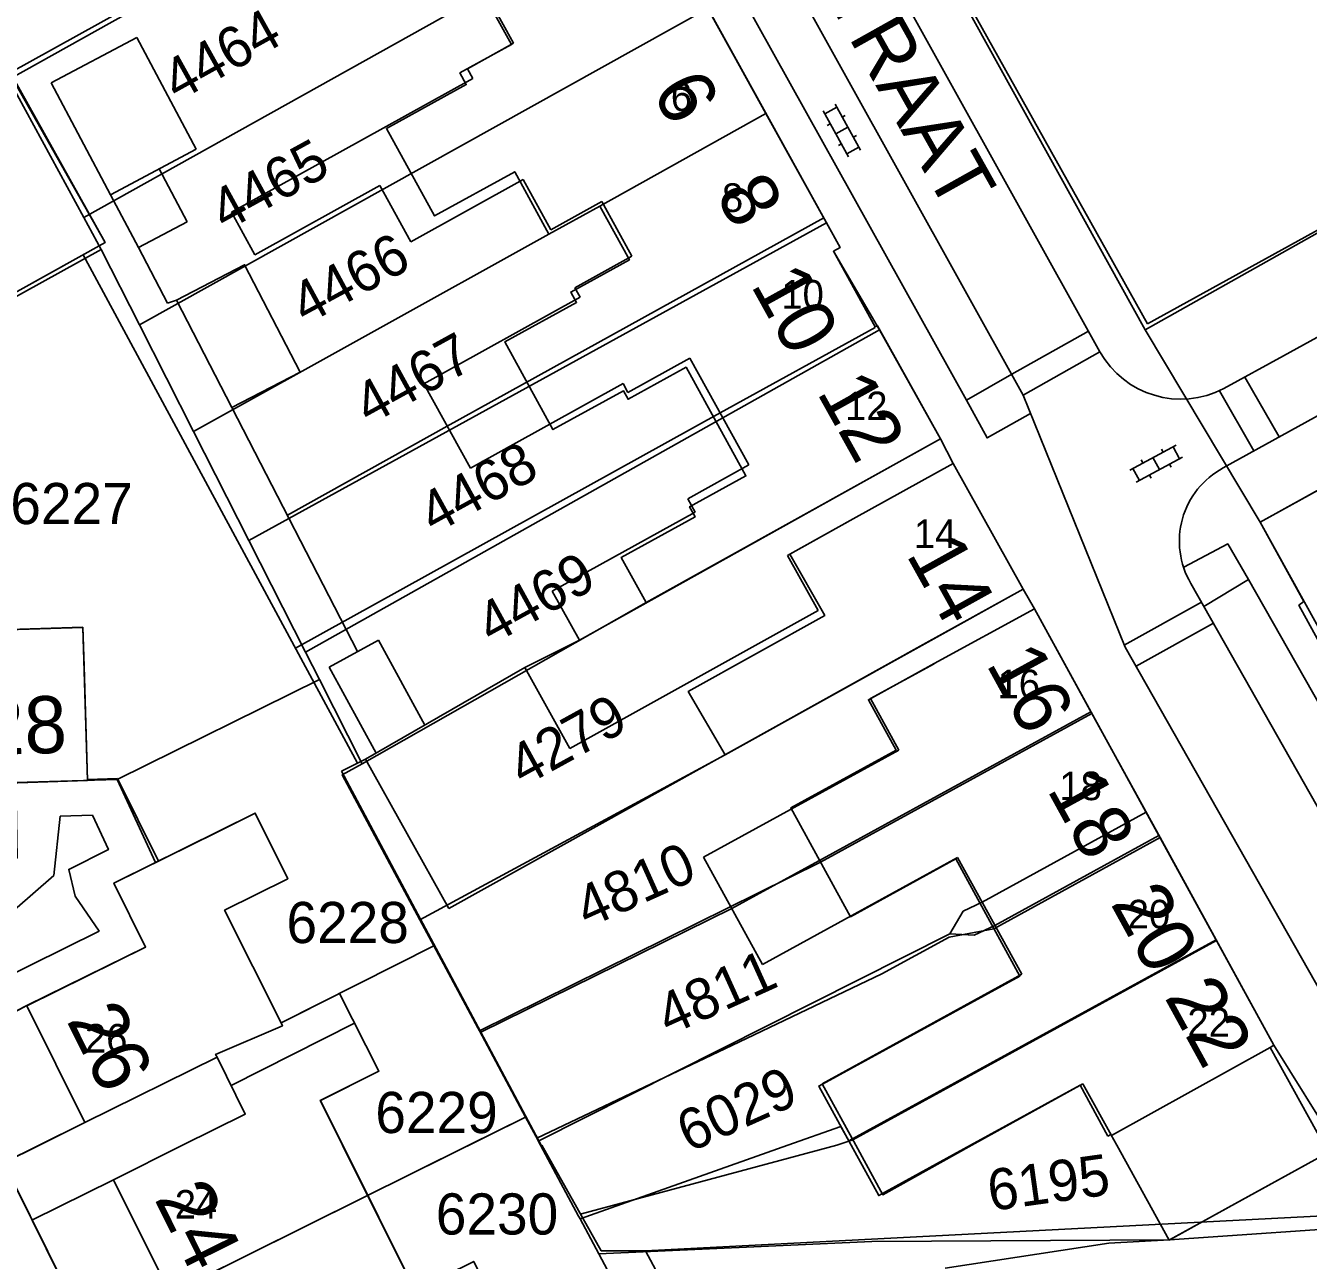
# Model space of a CAD drawing. Extents: x 148816 to 151297, y 399515 to 402500.
# Drawn here: x 150198.8 to 150254.9, y 399995 to 400049 of the extents above; entities that cross this region are included whole.
import ezdxf

# ---------------------------------------------------------------- set-up
doc = ezdxf.new("R2010")
doc.units = 0
for name, color, linetype in [('B01 Hoofdgebouw  [D] Norm', 7, 'Continuous'), ('B01 Hoofdgebouw  [T] Norm', 7, 'Continuous'), ('B01 hoofgebouw', 7, 'Continuous'), ('B02 Bijgebouw  [D] Norm', 7, 'Continuous'), ('B07 Tussenmuur  [D] Norm', 7, 'Continuous'), ('G01 perceelsgrens', 7, 'Continuous'), ('S02 Open verharding  Norm', 7, 'Continuous'), ('T04 Haag heg  [D] Gem', 7, 'Continuous'), ('T09 Insteek water  [D] Norm', 7, 'Continuous'), ('V00 Kant verharding algemeen  [T] Norm', 7, 'Continuous'), ('V00 Kant verharding algemeen secundair  [T] Gem', 7, 'Continuous'), ('V06 Kant onverhard  [T] Gem', 7, 'Continuous'), ('Z01 perceelnummer', 7, 'Continuous'), ('Z02 huisnummer', 7, 'Continuous'), ('Z02 Huisnummer  [Tekst] Norm', 7, 'Continuous'), ('Z06 straatnaam', 7, 'Continuous')]:
    doc.layers.add(name, color=color, linetype=linetype)

msp = doc.modelspace()

# ---------------------------------------------------------------- linework, layer by layer
at = {"layer": 'B01 Hoofdgebouw  [D] Norm'}
for p, q in [((150198.007, 400046.867), (150209.022, 400052.993)), ((150220.109, 400048.214), (150217.755, 400052.466)), ((150218.088, 400047.095), (150220.109, 400048.214)), ((150218.326, 400046.665), (150218.088, 400047.095)), ((150202.24, 400039.49), (150198.106, 400046.922)), ((150207.765, 400040.82), (150218.326, 400046.665)), ((150204.609, 400042.718), (150205.838, 400040.401)), ((150214.252, 400041.98), (150208.794, 400038.96)), ((150215.611, 400039.525), (150214.252, 400041.98)), ((150220.524, 400042.245), (150215.611, 400039.525)), ((150221.74, 400040.049), (150220.524, 400042.245)), ((150203.703, 400039.268), (150202.474, 400041.586)), ((150223.964, 400041.28), (150221.74, 400040.049)), ((150225.285, 400038.894), (150223.964, 400041.28)), ((150205.838, 400040.401), (150203.703, 400039.268)), ((150208.794, 400038.96), (150207.765, 400040.82)), ((150185.558, 400030.21), (150202.24, 400039.49)), ((150222.795, 400037.515), (150225.285, 400038.894)), ((150223.027, 400037.096), (150222.795, 400037.515)), ((150216.179, 400033.304), (150223.027, 400037.096)), ((150227.817, 400034.436), (150225.11, 400032.938)), ((150230.403, 400029.763), (150227.817, 400034.436)), ((150218.218, 400029.622), (150216.179, 400033.304)), ((150224.898, 400033.321), (150218.218, 400029.622)), ((150225.11, 400032.938), (150224.898, 400033.321)), ((150227.729, 400028.283), (150230.403, 400029.763)), ((150222.99, 400022.096), (150234.413, 400028.465)), ((150228.052, 400027.699), (150227.729, 400028.283)), ((150221.802, 400024.242), (150228.052, 400027.699)), ((150232.088, 400025.801), (150234.961, 400027.399)), ((150233.427, 400023.394), (150232.088, 400025.801)), ((150222.99, 400022.096), (150221.802, 400024.242)), ((150222.576, 400017.358), (150233.427, 400023.394)), ((150217.27, 400010.354), (150238.021, 400021.899)), ((150213.636, 400016.885), (150220.602, 400020.907)), ((150220.602, 400020.907), (150222.576, 400017.358)), ((150235.719, 400019.537), (150238.503, 400021.064)), ((150236.955, 400017.284), (150235.719, 400019.537)), ((150228.419, 400012.601), (150236.955, 400017.284)), ((150213.636, 400016.885), (150217.27, 400010.354)), ((150247.771, 400014.57), (150240.601, 400010.638)), ((150248.333, 400013.546), (150241.163, 400009.614)), ((150230.996, 400007.904), (150228.419, 400012.601)), ((150239.532, 400012.587), (150230.996, 400007.904)), ((150242.334, 400007.48), (150239.532, 400012.587)), ((150233.601, 400002.689), (150242.334, 400007.48)), ((150246.26, 400000.426), (150253.2, 400004.27)), ((150235.076, 400000), (150233.601, 400002.689)), ((150240.149, 400000), (150245.005, 400002.691)), ((150245.005, 400002.691), (150246.26, 400000.426))]:
    msp.add_line(p, q, dxfattribs=at)
at = {"layer": 'B01 Hoofdgebouw  [T] Norm'}
for p, q in [((150234.39, 400039.27), (150227.89, 400051.03)), ((150234.1, 400039.11), (150234.39, 400039.27)), ((150235.92, 400035.8), (150234.1, 400039.11)), ((150236.02, 400035.85), (150235.92, 400035.8)), ((150238.78, 400030.9), (150236.02, 400035.85)), ((150234.41, 400028.47), (150238.78, 400030.9)), ((150252.77, 400027.26), (150259.53, 400031.01)), ((150239.33, 400029.83), (150234.96, 400027.4)), ((150242.39, 400024.33), (150239.33, 400029.83)), ((150254.67, 400023.79), (150252.77, 400027.26)), ((150238.02, 400021.9), (150242.39, 400024.33)), ((150238.5, 400021.07), (150242.89, 400023.47)), ((150242.89, 400023.47), (150253.36, 400004.38)), ((150254.46, 400023.62), (150254.67, 400023.79)), ((150255.68, 400021.4), (150254.46, 400023.62)), ((150201.272, 400022.655), (150181.03, 400022.028)), ((150201.272, 400022.655), (150201.479, 400015.96)), ((150201.479, 400015.96), (150195.375, 400015.756)), ((150208.812, 400014.525), (150202.627, 400011.466)), ((150210.231, 400011.657), (150208.812, 400014.525)), ((150207.465, 400010.279), (150210.231, 400011.657)), ((150202.627, 400011.466), (150204.01, 400008.67)), ((150207.465, 400010.279), (150209.944, 400005.351)), ((150204.01, 400008.67), (150198.824, 400006.105)), ((150209.944, 400005.351), (150212.496, 400006.642)), ((150212.496, 400006.642), (150214.218, 400003.238)), ((150201.355, 400000.987), (150198.824, 400006.105)), ((150253.36, 400004.38), (150253.2, 400004.27)), ((150207.143, 400003.85), (150201.355, 400000.987)), ((150207.143, 400003.85), (150208.373, 400001.363)), ((150253.2, 400004.27), (150255.565, 400000)), ((150211.655, 400001.958), (150214.218, 400003.238)), ((150211.655, 400001.958), (150212.631, 400000)), ((150208.372, 400001.365), (150205.633, 400000)), ((150205.633, 400000), (150202.606, 399998.491)), ((150212.631, 400000), (150215.798, 399993.644)), ((150255.74, 399999.68), (150251.36, 399997.27)), ((150202.606, 399998.491), (150207.56, 399988.55))]:
    msp.add_line(p, q, dxfattribs=at)
at = {"layer": 'B01 hoofgebouw'}
for points in [[(150169.09, 400048.69), (150171.369, 400044.618), (150177.805, 400048.221), (150179.199, 400045.731), (150183.06, 400047.893), (150189.217, 400036.824), (150183.613, 400033.707), (150185.558, 400030.21), (150202.24, 400039.49), (150190.33, 400060.58)], [(150234.41, 400028.47), (150238.78, 400030.9), (150236.02, 400035.85), (150235.92, 400035.8), (150234.1, 400039.11), (150234.39, 400039.27), (150227.89, 400051.03), (150227.61, 400050.87), (150225.79, 400054.18), (150225.89, 400054.23), (150223.15, 400059.18), (150218.77, 400056.76)], [(150217.672, 400052.405), (150220.012, 400048.149), (150217.761, 400046.912), (150218.041, 400046.403), (150214.547, 400044.482), (150216.65, 400040.658), (150220.157, 400042.586), (150221.655, 400039.862), (150223.884, 400041.087), (150225.176, 400038.737), (150222.612, 400037.327), (150222.864, 400036.869), (150219.723, 400035.142), (150221.828, 400031.312), (150224.913, 400033.008), (150225.116, 400032.639), (150227.655, 400034.035), (150230.267, 400029.284), (150227.805, 400027.93), (150228.048, 400027.488), (150224.821, 400025.713), (150225.905, 400023.741), (150234.41, 400028.47)], [(150267.14, 400011.57), (150262.77, 400009.14), (150260.84, 400012.62), (150260.61, 400012.49), (150259.37, 400014.72), (150259.51, 400014.8), (150255.83, 400021.48), (150255.68, 400021.4), (150254.46, 400023.62), (150254.67, 400023.79), (150252.77, 400027.26), (150259.53, 400031.01), (150260.79, 400028.73), (150269.62, 400033.65), (150269.921, 400033.111), (150271.89, 400034.2), (150270.35, 400036.98), (150273.44, 400038.69), (150275.85, 400034.31)], [(150238.02, 400021.9), (150242.39, 400024.33), (150239.33, 400029.83), (150234.96, 400027.4)], [(150234.96, 400027.4), (150232.19, 400025.86), (150233.72, 400023.179), (150227.747, 400019.847), (150229.358, 400017.083), (150238.02, 400021.9)], [(150255.563, 400000), (150253.2, 400004.27), (150253.36, 400004.38), (150242.89, 400023.47), (150238.5, 400021.07)], [(150201.27, 400022.66), (150181.03, 400022.03)], [(150201.27, 400022.66), (150201.325, 400020.957)], [(150181.083, 400020.319), (150181.238, 400015.322), (150184.277, 400015.416), (150184.404, 400011.314), (150195.501, 400011.658), (150195.375, 400015.756), (150201.479, 400015.96), (150201.325, 400020.957)], [(150238.5, 400021.07), (150235.63, 400019.492), (150236.842, 400017.28), (150232.233, 400014.755), (150234.839, 400009.997), (150239.449, 400012.522), (150242.253, 400007.403), (150233.456, 400002.584), (150234.871, 400000)], [(150212.635, 400000), (150211.66, 400001.96), (150214.22, 400003.24), (150212.5, 400006.64), (150209.94, 400005.35), (150207.47, 400010.28), (150210.23, 400011.66), (150208.81, 400014.53), (150207.108, 400013.682)], [(150207.108, 400013.682), (150202.627, 400011.466), (150204.01, 400008.67), (150198.824, 400006.105), (150201.355, 400000.987), (150207.143, 400003.85), (150208.372, 400001.365), (150205.633, 400000)], [(150240.095, 400000), (150244.883, 400002.623), (150246.1, 400000.402)], [(150246.1, 400000.402), (150246.232, 400000.474)], [(150246.232, 400000.474), (150246.493, 400000)], [(150205.633, 400000), (150202.606, 399998.491), (150207.56, 399988.55), (150213.32, 399991.421), (150215.846, 399986.318), (150210.088, 399983.468), (150215.017, 399973.51), (150219.498, 399975.728)], [(150223.64, 399977.78), (150219.12, 399986.92), (150221.7, 399988.2), (150218.37, 399994.92), (150215.8, 399993.64), (150212.635, 400000)], [(150234.871, 400000), (150236.077, 399997.799), (150240.095, 400000)], [(150246.493, 400000), (150248.778, 399995.848), (150251.36, 399997.27)], [(150251.36, 399997.27), (150255.74, 399999.68), (150255.563, 400000)]]:
    msp.add_lwpolyline(points, dxfattribs=at)
at = {"layer": 'B02 Bijgebouw  [D] Norm'}
for p, q in [((150199.881, 400046.475), (150203.634, 400048.465)), ((150203.634, 400048.465), (150206.227, 400043.576)), ((150202.474, 400041.586), (150199.881, 400046.475)), ((150206.227, 400043.576), (150202.474, 400041.586)), ((150212.04, 400020.921), (150214.206, 400022.1)), ((150214.206, 400022.1), (150216.228, 400018.382)), ((150214.092, 400017.148), (150212.04, 400020.921))]:
    msp.add_line(p, q, dxfattribs=at)
msp.add_lwpolyline([(150207.793, 400032.274), (150205.36, 400036.973), (150208.344, 400038.518), (150210.777, 400033.819)], close=True, dxfattribs=at)
msp.add_lwpolyline([(150240.149, 400000), (150236.257, 399997.83), (150235.076, 400000)], dxfattribs=at)
at = {"layer": 'B07 Tussenmuur  [D] Norm'}
for p, q in [((150233.674, 400040.566), (150217.2, 400031.461)), ((150233.674, 400040.566), (150217.2, 400031.461)), ((150235.931, 400035.78), (150229.14, 400032.046)), ((150235.931, 400035.78), (150229.14, 400032.046)), ((150245.36, 400018.966), (150229.653, 400010.351)), ((150245.36, 400018.966), (150229.653, 400010.351)), ((150250.852, 400008.953), (150234.949, 400000.231)), ((150250.852, 400008.953), (150234.949, 400000.231)), ((150213.156, 400005.337), (150207.758, 400002.606)), ((150213.156, 400005.337), (150207.758, 400002.606)), ((150213.726, 399997.802), (150205.087, 399993.513)), ((150213.726, 399997.802), (150205.087, 399993.513))]:
    msp.add_line(p, q, dxfattribs=at)
at = {"layer": 'G01 perceelsgrens'}
for points in [[(150321.59, 400076.47), (150308, 400069.2), (150269.6, 400047.96), (150247.733, 400035.669)], [(150247.733, 400035.669), (150235.511, 400057.754)], [(150225.856, 400054.291), (150201.315, 400040.582)], [(150207.073, 400051.69), (150198.036, 400046.619)], [(150228.608, 400049.73), (150203.744, 400035.892)], [(150231.143, 400045.144), (150228.608, 400049.73)], [(150201.315, 400040.582), (150198.036, 400046.619)], [(150231.143, 400045.144), (150223.884, 400041.087), (150221.655, 400039.862), (150206.108, 400031.232)], [(150233.789, 400040.357), (150231.143, 400045.144)], [(150202.074, 400039.184), (150201.315, 400040.582)], [(150233.789, 400040.357), (150208.535, 400026.449)], [(150236.12, 400035.671), (150234.1, 400039.11), (150234.39, 400039.27), (150233.789, 400040.357)], [(150189.018, 400031.962), (150202.074, 400039.184)], [(150202.074, 400039.184), (150203.744, 400035.892)], [(150252.77, 400027.26), (150259.53, 400031.01), (150274.51, 400039.29)], [(150203.744, 400035.892), (150206.108, 400031.232)], [(150236.12, 400035.671), (150211.007, 400021.575)], [(150238.78, 400030.9), (150236.12, 400035.671)], [(150247.733, 400035.669), (150252.77, 400027.26)], [(150206.108, 400031.232), (150208.535, 400026.449)], [(150238.78, 400030.9), (150225.905, 400023.741), (150213.485, 400016.692)], [(150242.39, 400024.33), (150239.33, 400029.83), (150238.78, 400030.9)], [(150255.302, 400022.673), (150252.77, 400027.26)], [(150208.535, 400026.449), (150211.007, 400021.575)], [(150242.39, 400024.33), (150229.358, 400017.083), (150216.007, 400009.866)], [(150242.89, 400023.47), (150242.39, 400024.33)], [(150245.405, 400018.884), (150242.89, 400023.47)], [(150211.007, 400021.575), (150211.613, 400020.381)], [(150202.769, 400016.002), (150211.613, 400020.381)], [(150211.613, 400020.381), (150213.485, 400016.692)], [(150245.405, 400018.884), (150233.536, 400012.379), (150218.614, 400004.998)], [(150248.382, 400013.456), (150245.405, 400018.884)], [(150213.485, 400016.692), (150212.612, 400016.205), (150216.007, 400009.866)], [(150190.038, 400008.511), (150193.08, 400008.61), (150195.55, 400010.11), (150198.39, 400012.57), (150198.34, 400015.87), (150202.769, 400016.002)], [(150196.99, 400005.18), (150198.82, 400006.11), (150204.01, 400008.67), (150202.63, 400011.47), (150204.449, 400012.371), (150202.769, 400016.002)], [(150248.382, 400013.456), (150241.119, 400009.473), (150239.16, 400009.095), (150236.215, 400007.495), (150229.651, 400004.365), (150221.123, 400000.315)], [(150250.835, 400008.983), (150248.382, 400013.456)], [(150216.007, 400009.866), (150216.622, 400008.717)], [(150250.835, 400008.983), (150234.767, 400000.192), (150234.42, 400000.825), (150232.099, 400000)], [(150253.36, 400004.38), (150250.835, 400008.983)], [(150199.37, 400000), (150201.36, 400000.99), (150207.14, 400003.85), (150207.078, 400003.975), (150210.001, 400005.229), (150209.94, 400005.35), (150216.622, 400008.717)], [(150216.622, 400008.717), (150218.543, 400005.13)], [(150218.543, 400005.13), (150218.614, 400004.998)], [(150218.614, 400004.998), (150220.632, 400001.231)], [(150256.08, 400000), (150253.36, 400004.38)], [(150218.153, 400000), (150220.632, 400001.231)], [(150220.632, 400001.231), (150221.076, 400000.403)], [(150197.817, 399999.227), (150199.37, 400000)], [(150201.516, 399991.739), (150218.153, 400000)], [(150221.076, 400000.403), (150221.123, 400000.315)], [(150221.123, 400000.315), (150221.292, 400000)], [(150221.292, 400000), (150222.951, 399996.902)], [(150232.099, 400000), (150223.02, 399996.773)], [(150255.74, 399999.68), (150248.798, 399995.86)], [(150197.817, 399999.227), (150201.516, 399991.739)], [(150222.951, 399996.902), (150223.02, 399996.773)], [(150223.02, 399996.773), (150223.834, 399995.252)], [(150258.107, 399996.501), (150248.798, 399995.86)], [(150248.798, 399995.86), (150235.782, 399995.794), (150223.834, 399995.252)], [(150248.798, 399995.86), (150246.146, 399995.711), (150238.992, 399994.623)], [(150223.834, 399995.252), (150224.598, 399993.826)]]:
    msp.add_lwpolyline(points, dxfattribs=at)
at = {"layer": 'S02 Open verharding  Norm'}
for p, q in [((150234.243, 400045.41), (150233.719, 400045.119)), ((150235.286, 400043.53), (150234.171, 400045.541)), ((150234.761, 400043.239), (150233.646, 400045.25)), ((150234.486, 400044.973), (150234.617, 400045.045)), ((150233.83, 400044.609), (150233.961, 400044.682)), ((150234.204, 400044.245), (150234.728, 400044.535)), ((150234.315, 400043.735), (150234.446, 400043.807)), ((150235.213, 400043.661), (150234.689, 400043.37)), ((150234.971, 400044.098), (150235.102, 400044.171)), ((150247.061, 400029.54), (150249.087, 400030.63)), ((150248.443, 400030.454), (150248.514, 400030.322)), ((150249.239, 400030.031), (150248.954, 400030.559)), ((150247.478, 400029.083), (150247.193, 400029.611)), ((150247.345, 400029.012), (150249.371, 400030.102)), ((150247.562, 400029.98), (150247.634, 400029.848)), ((150248.074, 400030.085), (150248.358, 400029.557)), ((150248.798, 400029.794), (150248.87, 400029.662)), ((150247.918, 400029.32), (150247.989, 400029.188))]:
    msp.add_line(p, q, dxfattribs=at)
at = {"layer": 'T04 Haag heg  [D] Gem'}
for p, q in [((150203.703, 400039.268), (150204.968, 400036.841)), ((150201.286, 400038.959), (150213.282, 400016.709)), ((150204.968, 400036.841), (150205.36, 400036.973)), ((150207.793, 400032.274), (150213.289, 400021.601)), ((150210.574, 400021.743), (150229.14, 400032.046)), ((150210.216, 400027.568), (150217.2, 400031.461)), ((150220.602, 400020.907), (150222.99, 400022.096)), ((150213.636, 400016.885), (150212.587, 400016.363)), ((150212.587, 400016.363), (150221.314, 400000)), ((150239.771, 400010.235), (150240.601, 400010.638)), ((150218.675, 400004.948), (150229.653, 400010.351)), ((150239.188, 400009.245), (150239.771, 400010.235)), ((150240.255, 400009.195), (150241.163, 400009.614)), ((150221.214, 400000.187), (150239.188, 400009.245)), ((150239.188, 400009.245), (150240.255, 400009.195)), ((150220.652, 400001.241), (150213.726, 399997.802)), ((150234.25, 400000), (150234.949, 400000.231))]:
    msp.add_line(p, q, dxfattribs=at)
for points in [[(150223.075, 399997.001), (150234.25, 400000)], [(150223.939, 399995.38), (150225.884, 399995.373), (150257.216, 399996.996)], [(150225.884, 399995.373), (150233.942, 399980.307), (150240.091, 399968.532)]]:
    msp.add_lwpolyline(points, dxfattribs=at)
at = {"layer": 'T09 Insteek water  [D] Norm'}
msp.add_line((150221.341, 400000), (150223.939, 399995.38), dxfattribs=at)
at = {"layer": 'V00 Kant verharding algemeen  [T] Norm'}
for p, q in [((150247.83, 400035.93), (150218.97, 400087.67)), ((150269.6, 400047.96), (150247.83, 400035.93)), ((150201.478, 400015.998), (150202.791, 400016.039)), ((150204.576, 400012.43), (150202.791, 400016.039)), ((150199.364, 400000), (150201.355, 400000.987)), ((150197.8, 399999.225), (150199.364, 400000)), ((150199.04, 399996.724), (150202.606, 399998.491))]:
    msp.add_line(p, q, dxfattribs=at)
for points in [[(150216.929, 400086.59), (150213.538, 400084.74), (150242.403, 400032.818), (150246.853, 400021.795), (150259.22, 400000)], [(150245.757, 400034.712), (150216.929, 400086.59)], [(150253.786, 400034.528), (150271.346, 400044.205), (150270.799, 400045.226), (150312.59, 400068.332), (150313.143, 400067.336), (150318.955, 400070.533), (150320.405, 400067.934), (150301.443, 400057.442)], [(150253.786, 400034.528), (150251.17, 400033.101)], [(150241.905, 400033.738), (150239.914, 400032.602), (150240.82, 400030.947), (150242.721, 400032.015)], [(150251.143, 400029.629), (150256.998, 400032.863)], [(150250.298, 400023.573), (150252.251, 400024.743), (150251.343, 400026.307), (150249.425, 400025.285)], [(150263.661, 400000), (150249.733, 400024.582)], [(150198.825, 400006.109), (150197.033, 400005.144)], [(150197.416, 400000), (150211.253, 399972.084)]]:
    msp.add_lwpolyline(points, dxfattribs=at)
for centre, radius, start, end in [((150249.293, 400036.695), 4.054, 209.2818, 297.5704), ((150252.859, 400026.429), 3.631, 118.2061, 210.576)]:
    msp.add_arc(centre, radius, start, end, dxfattribs=at)
at = {"layer": 'V00 Kant verharding algemeen secundair  [T] Gem'}
msp.add_line((150199.998, 400011.806), (150200.283, 400014.401), dxfattribs=at)
for points in [[(150241.897, 400033.734), (150245.256, 400035.614)], [(150245.757, 400034.712), (150242.404, 400032.816)], [(150253.601, 400030.987), (150252.093, 400033.604)], [(150250.979, 400033.007), (150252.488, 400030.377)], [(150246.818, 400021.883), (150250.196, 400023.754)], [(150250.721, 400022.835), (150247.332, 400020.951)], [(150199.998, 400011.806), (150196.54, 400008.791), (150193.709, 400007.085), (150194.454, 400005.653), (150201.98, 400009.367), (150200.937, 400010.9), (150200.65, 400012.066), (150202.388, 400012.932), (150201.69, 400014.44), (150200.283, 400014.401)]]:
    msp.add_lwpolyline(points, dxfattribs=at)
at = {"layer": 'V06 Kant onverhard  [T] Gem'}
for points in [[(150227.913, 400054.16), (150239.914, 400032.602)], [(150266.304, 400000), (150252.251, 400024.743)]]:
    msp.add_lwpolyline(points, dxfattribs=at)

# ---------------------------------------------------------------- texts
at = {"layer": 'Z01 perceelnummer'}
for s, rotation, p in [('4464', 29.0714, (150205.409, 400045.632)), ('4465', 28.7577, (150207.494, 400039.956)), ('4466', 28.4682, (150211.011, 400035.863)), ('4467', 28.7756, (150213.79, 400031.476)), ('4468', 28.8639, (150216.627, 400026.703)), ('4469', 28.8133, (150219.149, 400021.872)), ('4279', 28.7706, (150220.528, 400015.658)), ('4810', 24.1963, (150223.337, 400009.477)), ('4811', 24.3436, (150226.896, 400004.771)), ('6029', 24.2435, (150227.786, 399999.662)), ('6195', 7.9262, (150240.972, 399997.115))]:
    msp.add_text(s, height=1.8, rotation=rotation, dxfattribs=at).set_placement(p)
for s, p in [('6227', (150198.098, 400027.173)), ('6228', (150210.176, 400008.844)), ('6229', (150214.062, 400000.533)), ('6230', (150216.707, 399996.093))]:
    msp.add_text(s, height=1.8, dxfattribs=at).set_placement(p)
at = {"layer": 'Z02 huisnummer'}
for s, rotation, p in [('6', 298.9489, (150226.128, 400046.1)), ('8', 298.9489, (150228.914, 400041.589)), ('10', 298.9489, (150230.455, 400037.642)), ('12', 299.1548, (150233.345, 400032.946)), ('14', 299.0769, (150237.25, 400025.853)), ('16', 298.743, (150240.748, 400021.064)), ('28', 1.8347, (150196.888, 400017.059)), ('18', 298.743, (150243.415, 400015.569)), ('20', 298.743, (150246.193, 400010.585)), ('22', 298.743, (150248.55, 400006.487)), ('26', 296.4114, (150200.534, 400005.464)), ('24', 296.3087, (150204.377, 399997.666))]:
    msp.add_text(s, height=2.5, rotation=rotation, dxfattribs=at).set_placement(p)
at = {"layer": 'Z02 Huisnummer  [Tekst] Norm'}
for s, p in [('6', (150226.986, 400045.241)), ('8', (150229.223, 400040.831)), ('10', (150231.819, 400036.598)), ('12', (150234.605, 400031.721)), ('14', (150237.615, 400026.125)), ('16', (150241.275, 400019.555)), ('18', (150243.981, 400015.096)), ('20', (150246.968, 400009.486)), ('22', (150249.581, 400004.751)), ('26', (150201.361, 400004.055)), ('24', (150205.289, 399996.79))]:
    msp.add_text(s, height=1.25, dxfattribs=at).set_placement(p)
at = {"layer": 'Z06 straatnaam'}
for s, rotation, p in [('ONS DOELSTRAAT', 299.2828, (150224.199, 400067.283)), ('ELISABETH BAS', 295.796, (150194.076, 399997.117))]:
    msp.add_text(s, height=2.5, rotation=rotation, dxfattribs=at).set_placement(p)

doc.saveas('drawing.dxf')
